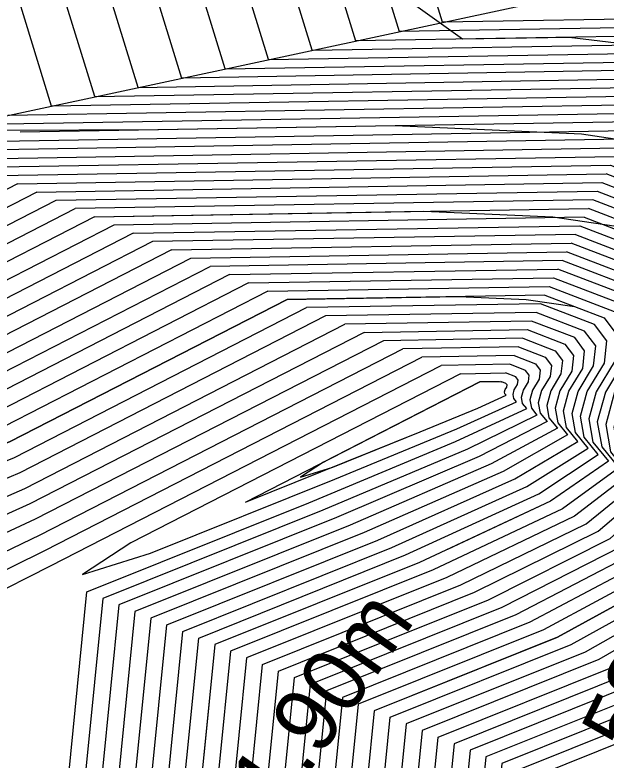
# Model space of a CAD drawing. Extents: x -866683 to -866410, y -1041951 to -1040252.
# Drawn here: x -866453.252 to -866450.494, y -1041911.251 to -1041907.774 of the extents above; entities that cross this region are included whole.
import ezdxf

# ---------------------------------------------------------------- set-up
doc = ezdxf.new("R2010")
doc.units = 0
for name, color, linetype in [('BODY', 7, 'Continuous'), ('BODY_2016', 7, 'Continuous'), ('BREAKLINE', 7, 'Continuous'), ('V-HL', 7, 'Continuous'), ('V-VEDL', 7, 'Continuous'), ('V_po_cm', 7, 'Continuous')]:
    doc.layers.add(name, color=color, linetype=linetype)

msp = doc.modelspace()

# ---------------------------------------------------------------- linework, layer by layer
at = {"layer": 'BREAKLINE'}
msp.add_lwpolyline([(-866451.679, -1041950.508), (-866455.618, -1041922.473), (-866456.719, -1041912.396), (-866455.207, -1041909.853), (-866453.752, -1041908.342), (-866450, -1041907.538), (-866447.7, -1041908.076), (-866445.165, -1041909.459), (-866437.422, -1041915.176), (-866426.565, -1041925.108), (-866438.22, -1041915.868), (-866445.312, -1041910.554), (-866447.7, -1041908.076)], dxfattribs=at)
at = {"layer": 'V-HL'}
for points in [[(-866452.1765, -1041910.0469), (-866451.3616, -1041909.7196), (-866451.0919, -1041909.6081), (-866450.9601, -1041909.5487), (-866450.9661, -1041909.5413), (-866450.9676, -1041909.5324), (-866450.9648, -1041909.5219), (-866450.9575, -1041909.5099), (-866450.9564, -1041909.5004), (-866450.9617, -1041909.4935), (-866450.9731, -1041909.4891), (-866450.9918, -1041909.4863), (-866451.0177, -1041909.4852), (-866451.0839, -1041909.4863)], [(-866452.1765, -1041910.0469), (-866451.0839, -1041909.4863)]]:
    msp.add_lwpolyline(points, dxfattribs=at)
at = {"layer": 'V-VEDL'}
for points in [[(-866452.8806, -1041908.7157), (-866453.5187, -1041909.0431), (-866453.8104, -1041909.1481), (-866454.0749, -1041909.1945), (-866454.3121, -1041909.1823), (-866455.2454, -1041908.4526), (-866456.8746, -1041907.0054), (-866459.1999, -1041904.8408), (-866461.1538, -1041903.0476), (-866462.7365, -1041901.6259), (-866465.1592, -1041899.5255)], [(-866464.8326, -1041901.9329), (-866458.5952, -1041907.3405), (-866456.4946, -1041909.1361), (-866455.4121, -1041910.0234), (-866455.3478, -1041910.0026), (-866455.2712, -1041909.9956), (-866455.1823, -1041910.0025), (-866455.0809, -1041910.0232), (-866454.8963, -1041910.0431), (-866454.6284, -1041910.0621), (-866454.2772, -1041910.0802), (-866453.8271, -1041909.9814), (-866453.2781, -1041909.7659), (-866451.9822, -1041909.101)], [(-866451.5942, -1041907.5759), (-866451.1645, -1041907.886), (-866450.666, -1041907.8776), (-866450.1599, -1041907.9389), (-866449.6462, -1041908.0699), (-866449.1248, -1041908.2706), (-866448.8875, -1041908.5864)], [(-866449.0899, -1041915.6585), (-866450.3375, -1041913.6448), (-866450.9179, -1041912.2014), (-866450.8312, -1041911.3283), (-866450.0774, -1041911.0256), (-866449.6433, -1041910.7396), (-866449.529, -1041910.4704), (-866449.7345, -1041910.218), (-866449.7882, -1041909.9122), (-866449.69, -1041909.5531), (-866449.4401, -1041909.1405), (-866449.4048, -1041908.8149), (-866449.584, -1041908.5763), (-866449.9779, -1041908.4247), (-866450.6093, -1041908.3298), (-866451.4782, -1041908.2917), (-866452.5847, -1041908.3103), (-866453.3252, -1041908.3136), (-866453.6997, -1041908.3014), (-866453.7167, -1041908.2462)], [(-866452.8806, -1041908.7157), (-866451.3442, -1041908.6899), (-866450.7433, -1041908.7154), (-866450.3097, -1041908.7795), (-866450.0432, -1041908.882), (-866449.922, -1041909.0434), (-866449.9459, -1041909.2636), (-866450.1149, -1041909.5427), (-866450.1813, -1041909.7856), (-866450.145, -1041909.9925), (-866450.006, -1041910.1632), (-866450.1981, -1041910.3914), (-866450.7214, -1041910.677), (-866451.5758, -1041911.0201), (-866451.6741, -1041912.0096), (-866451.0162, -1041913.6454), (-866449.6023, -1041915.9277), (-866448.4893, -1041917.4043)], [(-866451.9822, -1041909.101), (-866451.181, -1041909.0875), (-866450.8676, -1041909.1009), (-866450.6414, -1041909.1343), (-866450.5025, -1041909.1878), (-866450.4392, -1041909.2719), (-866450.4517, -1041909.3868), (-866450.5399, -1041909.5323), (-866450.5745, -1041909.659), (-866450.5555, -1041909.7669), (-866450.483, -1041909.8559), (-866450.753, -1041910.0431), (-866451.3654, -1041910.3284), (-866452.3203, -1041910.7119), (-866452.4302, -1041911.8178), (-866451.695, -1041913.6461), (-866450.1147, -1041916.1968), (-866448.8707, -1041917.8472)]]:
    msp.add_lwpolyline(points, dxfattribs=at)
at = {"layer": 'V_po_cm'}
for points in [[(-866453.2399, -1041908.5616), (-866453.6149, -1041908.754), (-866453.7863, -1041908.8157), (-866453.9418, -1041908.843), (-866454.0812, -1041908.8358), (-866455.3367, -1041907.7487), (-866457.7084, -1041905.5816), (-866464.6842, -1041899.0877)], [(-866453.1501, -1041908.6001), (-866453.5908, -1041908.8263), (-866453.7924, -1041908.8988), (-866453.975, -1041908.9309), (-866454.1389, -1041908.9224), (-866455.3139, -1041907.9246), (-866457.5, -1041905.9376), (-866463.8944, -1041899.9848)], [(-866463.1047, -1041900.8819), (-866457.2915, -1041906.2935), (-866455.291, -1041908.1006), (-866454.1967, -1041909.009), (-866454.0083, -1041909.0188), (-866453.7984, -1041908.9819), (-866453.5668, -1041908.8985), (-866453.0603, -1041908.6387)], [(-866462.3149, -1041901.779), (-866457.0831, -1041906.6495), (-866455.2682, -1041908.2766), (-866454.2544, -1041909.0957), (-866454.0416, -1041909.1066), (-866453.8044, -1041909.065), (-866453.5427, -1041908.9708), (-866452.9704, -1041908.6772)], [(-866452.7907, -1041908.7543), (-866453.4946, -1041909.1154), (-866453.8164, -1041909.2312), (-866454.1082, -1041909.2824), (-866454.3699, -1041909.2689), (-866455.2225, -1041908.6286), (-866456.6662, -1041907.3614), (-866460.7354, -1041903.5732)], [(-866451.2574, -1041907.8074), (-866452.3036, -1041904.4146)], [(-866452.7009, -1041908.7928), (-866453.4705, -1041909.1876), (-866453.8225, -1041909.3143), (-866454.1415, -1041909.3703), (-866454.4276, -1041909.3556), (-866455.1997, -1041908.8046), (-866456.4577, -1041907.7173), (-866459.9456, -1041904.4703)], [(-866452.4213, -1041904.7339), (-866451.4602, -1041907.8509)], [(-866452.5391, -1041905.0532), (-866451.663, -1041907.8944)], [(-866452.6111, -1041908.8313), (-866453.4465, -1041909.2599), (-866453.8285, -1041909.3975), (-866454.1748, -1041909.4582), (-866454.4854, -1041909.4422), (-866455.1769, -1041908.9805), (-866456.2493, -1041908.0733), (-866459.1558, -1041905.3675)], [(-866451.8659, -1041907.9378), (-866452.6569, -1041905.3725)], [(-866452.0687, -1041907.9813), (-866452.7746, -1041905.6918)], [(-866452.2715, -1041908.0247), (-866452.8924, -1041906.0111)], [(-866452.5212, -1041908.8699), (-866453.4224, -1041909.3322), (-866453.8345, -1041909.4806), (-866454.2081, -1041909.5461), (-866454.5431, -1041909.5288), (-866455.154, -1041909.1565), (-866456.0408, -1041908.4292), (-866458.3661, -1041906.2646)], [(-866453.0101, -1041906.3304), (-866452.4743, -1041908.0682)], [(-866452.6771, -1041908.1117), (-866453.1279, -1041906.6497)], [(-866452.8799, -1041908.1551), (-866453.2456, -1041906.969)], [(-866457.5763, -1041907.1617), (-866455.8324, -1041908.7852), (-866455.1312, -1041909.3325), (-866454.6009, -1041909.6154), (-866454.2414, -1041909.634), (-866453.8405, -1041909.5637), (-866453.3984, -1041909.4045), (-866452.4314, -1041908.9084)], [(-866453.3634, -1041907.2883), (-866453.0827, -1041908.1986)], [(-866450.1267, -1041907.7884), (-866451.2574, -1041907.8074)], [(-866450.1471, -1041907.8288), (-866451.4602, -1041907.8509)], [(-866450.1675, -1041907.8692), (-866451.663, -1041907.8944)], [(-866451.8659, -1041907.9378), (-866450.1879, -1041907.9096)], [(-866452.0687, -1041907.9813), (-866450.2084, -1041907.9499)], [(-866452.2715, -1041908.0247), (-866450.2288, -1041907.9903)], [(-866450.2492, -1041908.0307), (-866452.4743, -1041908.0682)], [(-866456.7865, -1041908.0588), (-866455.6239, -1041909.1411), (-866455.1084, -1041909.5085), (-866454.6586, -1041909.7021), (-866454.2747, -1041909.7219), (-866453.8466, -1041909.6468), (-866453.3743, -1041909.4768), (-866452.3416, -1041908.9469)], [(-866452.6771, -1041908.1117), (-866450.2696, -1041908.0711)], [(-866452.8799, -1041908.1551), (-866450.2901, -1041908.1115)], [(-866453.0827, -1041908.1986), (-866450.3105, -1041908.1519)], [(-866453.2855, -1041908.242), (-866450.3309, -1041908.1923)], [(-866453.4883, -1041908.2855), (-866450.3514, -1041908.2327)], [(-866450.3718, -1041908.273), (-866453.227, -1041908.3211)], [(-866453.6891, -1041908.369), (-866450.3922, -1041908.3134)], [(-866450.3922, -1041908.3134), (-866449.63, -1041908.6069), (-866449.4565, -1041908.8378), (-866449.4907, -1041909.1528), (-866449.7325, -1041909.552), (-866449.8275, -1041909.8996), (-866449.7755, -1041910.1955), (-866449.5767, -1041910.4397), (-866449.6988, -1041910.7048), (-866450.1418, -1041910.9907), (-866450.9057, -1041911.2975), (-866450.9935, -1041912.1822), (-866450.4054, -1041913.6449), (-866449.1412, -1041915.6855), (-866448.146, -1041917.0057)], [(-866450.4126, -1041908.3538), (-866453.5993, -1041908.4075)], [(-866450.4126, -1041908.3538), (-866449.6759, -1041908.6374), (-866449.5082, -1041908.8606), (-866449.5413, -1041909.1651), (-866449.775, -1041909.551), (-866449.8668, -1041909.8869), (-866449.8166, -1041910.1729), (-866449.6244, -1041910.409), (-866449.7542, -1041910.67), (-866450.2062, -1041910.9559), (-866450.9801, -1041911.2667), (-866451.0692, -1041912.163), (-866450.4733, -1041913.6449), (-866449.1924, -1041915.7124), (-866448.1841, -1041917.05)], [(-866453.5094, -1041908.446), (-866450.4331, -1041908.3942)], [(-866450.4331, -1041908.3942), (-866449.7218, -1041908.668), (-866449.5599, -1041908.8835), (-866449.5918, -1041909.1774), (-866449.8175, -1041909.5499), (-866449.9061, -1041909.8743), (-866449.8576, -1041910.1504), (-866449.6721, -1041910.3783), (-866449.8097, -1041910.6352), (-866450.2706, -1041910.921), (-866451.0546, -1041911.2359), (-866451.1448, -1041912.1439), (-866450.5411, -1041913.645), (-866449.2436, -1041915.7393), (-866448.2223, -1041917.0943)], [(-866453.4196, -1041908.4846), (-866450.4535, -1041908.4346)], [(-866450.4535, -1041908.4346), (-866449.7677, -1041908.6986), (-866449.6117, -1041908.9063), (-866449.6424, -1041909.1897), (-866449.86, -1041909.5489), (-866449.9454, -1041909.8616), (-866449.8987, -1041910.1278), (-866449.7198, -1041910.3475), (-866449.8652, -1041910.6003), (-866450.335, -1041910.8862), (-866451.129, -1041911.205), (-866451.2204, -1041912.1247), (-866450.609, -1041913.6451), (-866449.2949, -1041915.7662), (-866448.2604, -1041917.1386)], [(-866453.3298, -1041908.5231), (-866450.4739, -1041908.475)], [(-866450.4739, -1041908.475), (-866449.8136, -1041908.7292), (-866449.6634, -1041908.9292), (-866449.693, -1041909.2021), (-866449.9025, -1041909.5479), (-866449.9847, -1041909.8489), (-866449.9397, -1041910.1052), (-866449.7675, -1041910.3168), (-866449.9207, -1041910.5655), (-866450.3994, -1041910.8513), (-866451.2035, -1041911.1742), (-866451.296, -1041912.1055), (-866450.6769, -1041913.6451), (-866449.3461, -1041915.7931), (-866448.2986, -1041917.1829)], [(-866453.2399, -1041908.5616), (-866450.4944, -1041908.5154)], [(-866448.3367, -1041917.2272), (-866449.3974, -1041915.82), (-866450.7447, -1041913.6452), (-866451.3716, -1041912.0863), (-866451.278, -1041911.1434), (-866450.4638, -1041910.8164), (-866449.9762, -1041910.5307), (-866449.8152, -1041910.2861), (-866449.9808, -1041910.0827), (-866450.0241, -1041909.8363), (-866449.945, -1041909.5468), (-866449.7436, -1041909.2144), (-866449.7151, -1041908.952), (-866449.8596, -1041908.7597), (-866450.4944, -1041908.5154)], [(-866453.1501, -1041908.6001), (-866450.5148, -1041908.5558)], [(-866450.5148, -1041908.5558), (-866449.9055, -1041908.7903), (-866449.7668, -1041908.9749), (-866449.7942, -1041909.2267), (-866449.9875, -1041909.5458), (-866450.0634, -1041909.8236), (-866450.0219, -1041910.0601), (-866449.8629, -1041910.2554), (-866450.0317, -1041910.4958), (-866450.5282, -1041910.7816), (-866451.3524, -1041911.1126), (-866451.4472, -1041912.0671), (-866450.8126, -1041913.6453), (-866449.4486, -1041915.8469), (-866448.3749, -1041917.2714)], [(-866453.0603, -1041908.6387), (-866450.5352, -1041908.5961)], [(-866450.5352, -1041908.5961), (-866449.9514, -1041908.8209), (-866449.8185, -1041908.9977), (-866449.8447, -1041909.239), (-866450.03, -1041909.5448), (-866450.1027, -1041909.8109), (-866450.0629, -1041910.0376), (-866449.9106, -1041910.2246), (-866450.0872, -1041910.461), (-866450.5926, -1041910.7467), (-866451.4269, -1041911.0818), (-866451.5228, -1041912.048), (-866450.8805, -1041913.6453), (-866449.4998, -1041915.8738), (-866448.413, -1041917.3157)], [(-866450.5556, -1041908.6365), (-866452.9704, -1041908.6772)], [(-866448.4512, -1041917.36), (-866449.5511, -1041915.9008), (-866450.9484, -1041913.6454), (-866451.5984, -1041912.0288), (-866451.5013, -1041911.0509), (-866450.657, -1041910.7119), (-866450.1427, -1041910.4262), (-866449.9583, -1041910.1939), (-866450.104, -1041910.015), (-866450.142, -1041909.7983), (-866450.0725, -1041909.5437), (-866449.8953, -1041909.2513), (-866449.8703, -1041909.0206), (-866449.9973, -1041908.8515), (-866450.5556, -1041908.6365)], [(-866452.8806, -1041908.7157), (-866450.5761, -1041908.6769)], [(-866451.4507, -1041910.9699), (-866450.7214, -1041910.677), (-866450.1981, -1041910.3914), (-866450.006, -1041910.1632), (-866450.145, -1041909.9925), (-866450.1813, -1041909.7856), (-866450.1149, -1041909.5427), (-866449.9459, -1041909.2636), (-866449.922, -1041909.0434), (-866450.0432, -1041908.882), (-866450.5761, -1041908.6769)], [(-866452.8806, -1041908.7157), (-866453.5187, -1041909.0431), (-866453.8104, -1041909.1481), (-866454.0749, -1041909.1945), (-866454.3121, -1041909.1823), (-866454.7581, -1041908.8336)], [(-866450.5965, -1041908.7173), (-866452.7907, -1041908.7543)], [(-866450.5965, -1041908.7173), (-866450.0892, -1041908.9126), (-866449.9737, -1041909.0663), (-866449.9965, -1041909.2759), (-866450.1574, -1041909.5416), (-866450.2206, -1041909.773), (-866450.1861, -1041909.9699), (-866450.0537, -1041910.1325), (-866450.2536, -1041910.3565), (-866450.7858, -1041910.6422), (-866451.6502, -1041910.9893), (-866451.7497, -1041911.9904), (-866451.0841, -1041913.6455), (-866449.6536, -1041915.9546), (-866448.5274, -1041917.4486)], [(-866452.7009, -1041908.7928), (-866450.6169, -1041908.7577)], [(-866450.6169, -1041908.7577), (-866450.1351, -1041908.9432), (-866450.0254, -1041909.0891), (-866450.0471, -1041909.2883), (-866450.1999, -1041909.5406), (-866450.2599, -1041909.7603), (-866450.2271, -1041909.9473), (-866450.1014, -1041910.1017), (-866450.3091, -1041910.3217), (-866450.8502, -1041910.6073), (-866451.7247, -1041910.9585), (-866451.8253, -1041911.9712), (-866451.152, -1041913.6456), (-866449.7048, -1041915.9815), (-866448.5656, -1041917.4929)], [(-866450.6373, -1041908.7981), (-866452.6111, -1041908.8313)], [(-866450.6373, -1041908.7981), (-866450.181, -1041908.9737), (-866450.0772, -1041909.112), (-866450.0976, -1041909.3006), (-866450.2424, -1041909.5396), (-866450.2993, -1041909.7476), (-866450.2682, -1041909.9248), (-866450.1491, -1041910.071), (-866450.3646, -1041910.2869), (-866450.9146, -1041910.5724), (-866451.7991, -1041910.9276), (-866451.9009, -1041911.952), (-866451.2199, -1041913.6456), (-866449.756, -1041916.0084), (-866448.6037, -1041917.5372)], [(-866452.5212, -1041908.8699), (-866450.6578, -1041908.8385)], [(-866448.6419, -1041917.5814), (-866449.8073, -1041916.0353), (-866451.2877, -1041913.6457), (-866451.9765, -1041911.9329), (-866451.8736, -1041910.8968), (-866450.979, -1041910.5376), (-866450.4201, -1041910.2521), (-866450.1968, -1041910.0403), (-866450.3092, -1041909.9022), (-866450.3386, -1041909.735), (-866450.2849, -1041909.5385), (-866450.1482, -1041909.3129), (-866450.1289, -1041909.1348), (-866450.2269, -1041909.0043), (-866450.6578, -1041908.8385)], [(-866452.4314, -1041908.9084), (-866450.6782, -1041908.8788)], [(-866448.68, -1041917.6257), (-866449.8585, -1041916.0622), (-866451.3556, -1041913.6458), (-866452.0521, -1041911.9137), (-866451.9481, -1041910.866), (-866451.0434, -1041910.5027), (-866450.4756, -1041910.2172), (-866450.2445, -1041910.0096), (-866450.3503, -1041909.8797), (-866450.3779, -1041909.7223), (-866450.3274, -1041909.5375), (-866450.1988, -1041909.3252), (-866450.1806, -1041909.1577), (-866450.2729, -1041909.0349), (-866450.6782, -1041908.8788)], [(-866450.6986, -1041908.9192), (-866452.3416, -1041908.9469)], [(-866448.7182, -1041917.67), (-866449.9098, -1041916.0892), (-866451.4235, -1041913.6458), (-866452.1277, -1041911.8945), (-866452.0225, -1041910.8352), (-866451.1078, -1041910.4679), (-866450.5311, -1041910.1824), (-866450.2922, -1041909.9788), (-866450.3913, -1041909.8571), (-866450.4172, -1041909.7097), (-866450.3699, -1041909.5365), (-866450.2494, -1041909.3375), (-866450.2323, -1041909.1805), (-866450.3188, -1041909.0655), (-866450.6986, -1041908.9192)], [(-866452.2517, -1041908.9854), (-866453.3503, -1041909.549), (-866453.8526, -1041909.7299), (-866454.3079, -1041909.8098), (-866454.7164, -1041909.7887), (-866455.0855, -1041909.6845), (-866455.4155, -1041909.4971), (-866455.9968, -1041908.9559)], [(-866452.2517, -1041908.9854), (-866450.7191, -1041908.9596)], [(-866448.7563, -1041917.7143), (-866449.961, -1041916.1161), (-866451.4914, -1041913.6459), (-866452.2033, -1041911.8753), (-866452.097, -1041910.8044), (-866451.1722, -1041910.433), (-866450.5866, -1041910.1476), (-866450.3399, -1041909.9481), (-866450.4324, -1041909.8346), (-866450.4565, -1041909.697), (-866450.4124, -1041909.5354), (-866450.2999, -1041909.3498), (-866450.2841, -1041909.2034), (-866450.3647, -1041909.096), (-866450.7191, -1041908.9596)], [(-866452.1619, -1041909.024), (-866453.3262, -1041909.6213), (-866453.8586, -1041909.813), (-866454.3412, -1041909.8977), (-866455.207, -1041909.853)], [(-866450.7395, -1041909), (-866450.4106, -1041909.1266), (-866450.3358, -1041909.2262), (-866450.3505, -1041909.3621), (-866450.4549, -1041909.5344), (-866450.4958, -1041909.6843), (-866450.4734, -1041909.812), (-866450.3876, -1041909.9174), (-866450.642, -1041910.1128), (-866451.2366, -1041910.3981), (-866452.1714, -1041910.7735), (-866452.279, -1041911.8561), (-866451.5592, -1041913.646), (-866450.0122, -1041916.143), (-866448.7945, -1041917.7586)], [(-866452.1619, -1041909.024), (-866450.7395, -1041909)], [(-866452.0721, -1041909.0625), (-866453.3021, -1041909.6936), (-866453.8429, -1041909.8972), (-866454.3092, -1041909.9889), (-866455.0933, -1041909.9485)], [(-866450.7599, -1041909.0404), (-866450.4565, -1041909.1572), (-866450.3875, -1041909.2491), (-866450.4011, -1041909.3745), (-866450.4974, -1041909.5333), (-866450.5352, -1041909.6717), (-866450.5145, -1041909.7894), (-866450.4353, -1041909.8866), (-866450.6975, -1041910.0779), (-866451.301, -1041910.3633), (-866452.2459, -1041910.7427), (-866452.3546, -1041911.837), (-866451.6271, -1041913.646), (-866450.0635, -1041916.1699), (-866448.8326, -1041917.8029)], [(-866452.0721, -1041909.0625), (-866450.7599, -1041909.0404)], [(-866450.7803, -1041909.0808), (-866451.9822, -1041909.101)], [(-866450.7803, -1041909.0808), (-866450.5025, -1041909.1878), (-866450.4392, -1041909.2719), (-866450.4517, -1041909.3868), (-866450.5399, -1041909.5323), (-866450.5745, -1041909.659), (-866450.5555, -1041909.7669), (-866450.483, -1041909.8559), (-866450.753, -1041910.0431), (-866451.2344, -1041910.2674)], [(-866451.9822, -1041909.101), (-866453.2781, -1041909.7659), (-866453.8271, -1041909.9814), (-866454.2772, -1041910.0802), (-866454.9796, -1041910.0439)], [(-866448.9089, -1041917.8914), (-866450.166, -1041916.2237), (-866451.7628, -1041913.6461), (-866452.5058, -1041911.7986), (-866452.3948, -1041910.6811), (-866451.4298, -1041910.2936), (-866450.8085, -1041910.0083), (-866450.5307, -1041909.8252), (-866450.5966, -1041909.7443), (-866450.6138, -1041909.6463), (-866450.5823, -1041909.5313), (-866450.5023, -1041909.3991), (-866450.4909, -1041909.2948), (-866450.5484, -1041909.2183), (-866450.8008, -1041909.1212)], [(-866450.8008, -1041909.1212), (-866451.8924, -1041909.1396)], [(-866454.866, -1041910.1394), (-866454.2452, -1041910.1714), (-866453.8114, -1041910.0657), (-866453.254, -1041909.8381), (-866451.8924, -1041909.1396)], [(-866448.947, -1041917.9357), (-866450.2172, -1041916.2506), (-866451.8307, -1041913.6462), (-866452.5814, -1041911.7794), (-866452.4693, -1041910.6502), (-866451.4943, -1041910.2587), (-866450.864, -1041909.9734), (-866450.5784, -1041909.7945), (-866450.6376, -1041909.7218), (-866450.6531, -1041909.6337), (-866450.6248, -1041909.5302), (-866450.5528, -1041909.4114), (-866450.5427, -1041909.3176), (-866450.5943, -1041909.2489), (-866450.8212, -1041909.1616)], [(-866450.8212, -1041909.1616), (-866451.8025, -1041909.1781)], [(-866451.8025, -1041909.1781), (-866453.23, -1041909.9104), (-866453.7956, -1041910.1499), (-866454.2132, -1041910.2627), (-866454.7523, -1041910.2349)], [(-866448.9852, -1041917.98), (-866450.2684, -1041916.2776), (-866451.8986, -1041913.6463), (-866452.657, -1041911.7602), (-866452.5437, -1041910.6194), (-866451.5587, -1041910.2238), (-866450.9195, -1041909.9386), (-866450.6261, -1041909.7637), (-866450.6787, -1041909.6992), (-866450.6924, -1041909.621), (-866450.6673, -1041909.5292), (-866450.6034, -1041909.4237), (-866450.5944, -1041909.3405), (-866450.6402, -1041909.2795), (-866450.8416, -1041909.2019)], [(-866450.8416, -1041909.2019), (-866451.7127, -1041909.2166)], [(-866454.6386, -1041910.3304), (-866454.1812, -1041910.354), (-866453.7799, -1041910.2341), (-866453.2059, -1041909.9827), (-866451.7127, -1041909.2166)], [(-866451.6229, -1041909.2551), (-866453.1819, -1041910.055), (-866453.7641, -1041910.3184), (-866454.1492, -1041910.4452), (-866454.5249, -1041910.4258)], [(-866450.862, -1041909.2423), (-866450.6861, -1041909.31), (-866450.6461, -1041909.3633), (-866450.654, -1041909.436), (-866450.7098, -1041909.5282), (-866450.7317, -1041909.6084), (-866450.7197, -1041909.6766), (-866450.6739, -1041909.733), (-866450.975, -1041909.9038), (-866451.6231, -1041910.189), (-866452.6182, -1041910.5886), (-866452.7326, -1041911.7411), (-866451.9665, -1041913.6463), (-866450.3197, -1041916.3045), (-866449.0233, -1041918.0243)], [(-866451.6229, -1041909.2551), (-866450.862, -1041909.2423)], [(-866451.533, -1041909.2937), (-866453.1578, -1041910.1273), (-866453.7484, -1041910.4026), (-866454.1172, -1041910.5365), (-866454.4112, -1041910.5213)], [(-866450.8825, -1041909.2827), (-866450.7321, -1041909.3406), (-866450.6978, -1041909.3862), (-866450.7046, -1041909.4483), (-866450.7523, -1041909.5271), (-866450.771, -1041909.5957), (-866450.7608, -1041909.6541), (-866450.7216, -1041909.7023), (-866451.0304, -1041909.869), (-866451.6875, -1041910.1541), (-866452.6926, -1041910.5578), (-866452.8082, -1041911.7219), (-866452.0343, -1041913.6464), (-866450.3709, -1041916.3314), (-866449.0615, -1041918.0686)], [(-866450.8825, -1041909.2827), (-866451.533, -1041909.2937)], [(-866454.2976, -1041910.6168), (-866454.0852, -1041910.6277), (-866453.7327, -1041910.4868), (-866453.1338, -1041910.1995), (-866451.4432, -1041909.3322)], [(-866450.9029, -1041909.3231), (-866450.778, -1041909.3712), (-866450.7496, -1041909.409), (-866450.7552, -1041909.4607), (-866450.7948, -1041909.5261), (-866450.8104, -1041909.583), (-866450.8018, -1041909.6315), (-866450.7693, -1041909.6716), (-866451.0859, -1041909.8341), (-866451.7519, -1041910.1193), (-866452.7671, -1041910.527), (-866452.8839, -1041911.7027), (-866452.1022, -1041913.6465), (-866450.4221, -1041916.3583), (-866449.0996, -1041918.1129)], [(-866450.9029, -1041909.3231), (-866451.4432, -1041909.3322)], [(-866454.1839, -1041910.7122), (-866454.0532, -1041910.719), (-866453.7169, -1041910.5711), (-866453.1097, -1041910.2718), (-866451.3534, -1041909.3707)], [(-866450.9233, -1041909.3635), (-866450.8239, -1041909.4018), (-866450.8013, -1041909.4319), (-866450.8057, -1041909.473), (-866450.8373, -1041909.525), (-866450.8497, -1041909.5704), (-866450.8429, -1041909.609), (-866450.817, -1041909.6408), (-866451.1414, -1041909.7993), (-866451.8163, -1041910.0844), (-866452.8415, -1041910.4961), (-866452.9595, -1041911.6835), (-866452.1701, -1041913.6465), (-866450.4734, -1041916.3852), (-866449.1378, -1041918.1572), (-866448.1632, -1041918.9624)], [(-866450.9233, -1041909.3635), (-866451.3534, -1041909.3707)], [(-866454.0702, -1041910.8077), (-866454.0212, -1041910.8102), (-866453.7012, -1041910.6553), (-866453.0856, -1041910.3441), (-866451.2635, -1041909.4093)], [(-866448.1918, -1041919.0146), (-866449.1759, -1041918.2014), (-866450.5246, -1041916.4121), (-866452.238, -1041913.6466), (-866453.0351, -1041911.6643), (-866452.916, -1041910.4653), (-866451.8807, -1041910.0496), (-866451.1969, -1041909.7645), (-866450.8647, -1041909.6101), (-866450.8839, -1041909.5864), (-866450.889, -1041909.5577), (-866450.8798, -1041909.524), (-866450.8563, -1041909.4853), (-866450.853, -1041909.4547), (-866450.8698, -1041909.4323), (-866450.9438, -1041909.4039)], [(-866450.9438, -1041909.4039), (-866451.2635, -1041909.4093)], [(-866451.1737, -1041909.4478), (-866452.7115, -1041910.2368), (-866452.9374, -1041910.3846), (-866452.6202, -1041910.2858), (-866451.76, -1041909.9404), (-866451.1907, -1041909.7049), (-866450.9124, -1041909.5794), (-866450.925, -1041909.5639), (-866450.9283, -1041909.5451), (-866450.9223, -1041909.523), (-866450.9069, -1041909.4976), (-866450.9047, -1041909.4776), (-866450.9157, -1041909.4629), (-866450.9642, -1041909.4443)], [(-866451.1737, -1041909.4478), (-866450.9642, -1041909.4443)], [(-866451.0839, -1041909.4863), (-866451.8123, -1041909.86), (-866451.9193, -1041909.9301), (-866451.769, -1041909.8833), (-866451.3616, -1041909.7196), (-866451.0919, -1041909.6081), (-866450.9601, -1041909.5487), (-866450.9661, -1041909.5413), (-866450.9676, -1041909.5324), (-866450.9648, -1041909.5219), (-866450.9575, -1041909.5099), (-866450.9564, -1041909.5004), (-866450.9617, -1041909.4935), (-866450.9846, -1041909.4847)], [(-866451.0839, -1041909.4863), (-866450.9846, -1041909.4847)], [(-866451.8889, -1041910.5386), (-866452.3203, -1041910.7119), (-866452.3716, -1041911.228)]]:
    msp.add_lwpolyline(points, dxfattribs=at)

# ---------------------------------------------------------------- texts
at = {"layer": 'BODY'}
msp.add_text('+', height=0.001, rotation=360, dxfattribs=at).set_placement((-866451.003, -1041909.521))
at = {"layer": 'BODY_2016'}
msp.add_text('+', height=0.001, rotation=360, dxfattribs=at).set_placement((-866451.003, -1041909.521))
at = {"layer": 'V_po_cm'}
for s, rotation, p in [('531.70m', 63.5632, (-866450.3516, -1041911.2419)), ('531.90m', 54.9989, (-866452.2782, -1041911.8791))]:
    msp.add_text(s, height=0.3, rotation=rotation, dxfattribs=at).set_placement(p)

doc.saveas('drawing.dxf')
